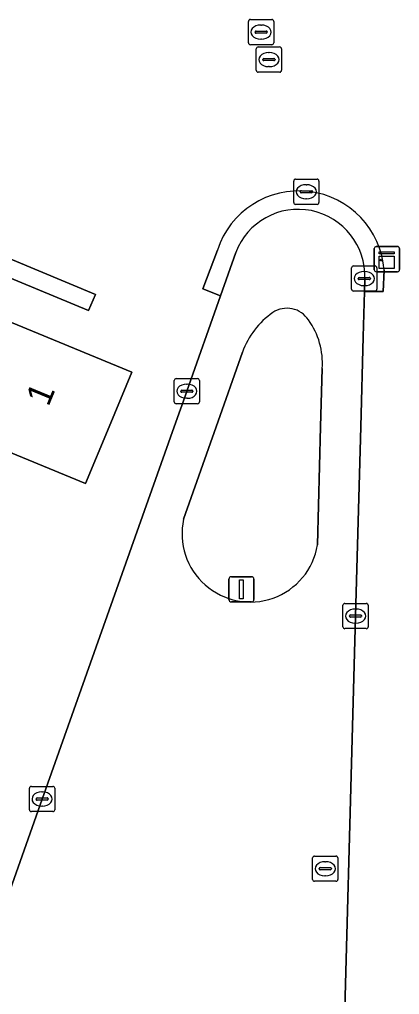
# Model space of a CAD drawing. Extents: x 160023 to 161302, y 384750 to 385707.
# Drawn here: x 160583.17 to 160598.24, y 384977.47 to 385016.17 of the extents above; entities that cross this region are included whole.
import ezdxf

# ---------------------------------------------------------------- set-up
doc = ezdxf.new("R2010")
doc.units = 0
for name, color, linetype in [('IMGEO_Brandkraan', 7, 'Continuous'), ('IMGEO_Erf', 7, 'Continuous'), ('IMGEO_Groenvoorziening', 7, 'Continuous'), ('IMGEO_Haag', 7, 'Continuous'), ('IMGEO_Kast', 7, 'Continuous'), ('IMGEO_Kolk', 7, 'Continuous'), ('IMGEO_Lichtmast', 7, 'Continuous'), ('IMGEO_Pand', 7, 'Continuous'), ('IMGEO_Pand_nummerreeks', 7, 'Continuous'), ('IMGEO_Rijbaan_lokaal_open', 7, 'Continuous'), ('IMGEO_Rioolput', 7, 'Continuous')]:
    doc.layers.add(name, color=color, linetype=linetype)

msp = doc.modelspace()

# ---------------------------------------------------------------- linework, layer by layer
at = {"layer": 'IMGEO_Brandkraan'}
for p, q in [((160594.797, 384982.034), (160594.797, 384982.886)), ((160594.872, 384982.96), (160595.724, 384982.96)), ((160595.285, 384982.74), (160595.31, 384982.74)), ((160595.798, 384982.886), (160595.798, 384982.034)), ((160595.056, 384982.454), (160595.056, 384982.466)), ((160595.494, 384982.417), (160595.096, 384982.417)), ((160595.099, 384982.503), (160595.497, 384982.503)), ((160595.54, 384982.466), (160595.54, 384982.454)), ((160595.724, 384981.96), (160594.872, 384981.96)), ((160595.308, 384982.18), (160595.283, 384982.18))]:
    msp.add_line(p, q, dxfattribs=at)
for points in [[(160594.797, 384982.034), (160594.797, 384982.886)], [(160594.872, 384982.96), (160595.724, 384982.96)], [(160595.798, 384982.886), (160595.798, 384982.034)], [(160595.724, 384981.96), (160594.872, 384981.96)]]:
    msp.add_lwpolyline(points, dxfattribs=at)
for centre, radius, start, end in [((160594.874, 384982.884), 0.0765, 91.552, 178.448), ((160594.874, 384982.884), 0.0765, 91.552, 178.448), ((160595.722, 384982.884), 0.0765, 1.552, 88.448), ((160595.722, 384982.884), 0.0765, 1.552, 88.448), ((160595.096, 384982.463), 0.0403, 85.8775, 175.7526), ((160595.093, 384982.453), 0.0366, 178.938, 274.7102), ((160595.497, 384982.46), 0.043, 264.8664, 352.4533), ((160595.501, 384982.465), 0.0386, 1.7309, 96.639), ((160594.874, 384982.036), 0.0765, 181.552, 268.448), ((160594.874, 384982.036), 0.0765, 181.552, 268.448), ((160595.722, 384982.036), 0.0765, 271.552, 358.448), ((160595.722, 384982.036), 0.0765, 271.552, 358.448)]:
    msp.add_arc(centre, radius, start, end, dxfattribs=at)
for centre, major_axis, ratio, start_param, end_param in [((160595.284, 384982.46), (-0.387, 0.002), 0.722429, 4.712389, 7.853982), ((160595.309, 384982.46), (-0.39, 0.002), 0.717154, 1.570796, 4.712389)]:
    msp.add_ellipse(centre, major_axis=major_axis, ratio=ratio, start_param=start_param, end_param=end_param, dxfattribs=at)
at = {"layer": 'IMGEO_Erf'}
for points in [[(160551.494, 384994.546), (160553.749, 385000), (160554.149, 385000.967), (160559.46, 385013.809), (160572.529, 385008.408), (160587.622, 385002.171), (160586.725, 385000), (160585.794, 384997.749), (160581.839, 384999.384), (160580.352, 384995.789), (160578.865, 384992.194), (160582.82, 384990.559), (160581.101, 384986.4), (160579.382, 384982.241), (160575.427, 384983.876), (160573.935, 384980.275), (160572.444, 384976.675)], [(160570.707, 384947.39), (160571.348, 384949.206), (160572.864, 384953.481), (160578.447, 384969.326), (160584.068, 384985.227), (160589.307, 385000), (160589.803, 385001.397), (160589.809, 385001.415), (160591.148, 385005.204), (160590.443, 385005.472), (160591.019, 385007.016)], [(160597.63, 385006.214), (160597.599, 385005.368), (160596.848, 385005.375), (160596.799, 385003.576), (160596.703, 385000), (160596.501, 384992.49), (160595.933, 384971.552), (160595.391, 384949.601)]]:
    msp.add_lwpolyline(points, dxfattribs=at)
msp.add_lwpolyline([(160573.447, 385009.785), (160573.728, 385010.449), (160586.183, 385005.251), (160585.915, 385004.616)], close=True, dxfattribs=at)
msp.add_arc((160594.247, 385005.973), 3.392, 4.08, 162.0861, dxfattribs=at)
at = {"layer": 'IMGEO_Groenvoorziening'}
msp.add_lwpolyline([(160586.183, 385005.251), (160573.728, 385010.449), (160573.447, 385009.785), (160585.915, 385004.616)], close=True, dxfattribs=at)
for points in [[(160591.019, 385007.016), (160590.443, 385005.472), (160591.148, 385005.204), (160591.751, 385006.921)], [(160596.865, 385005.886), (160596.848, 385005.375), (160597.599, 385005.368), (160597.63, 385006.214)], [(160592.015, 385002.963), (160590.972, 385000), (160589.682, 384996.333)], [(160594.993, 384995.31), (160595.115, 385000), (160595.176, 385002.317)]]:
    msp.add_lwpolyline(points, dxfattribs=at)
for centre, radius, start, end in [((160594.247, 385005.973), 3.392, 4.08, 162.0861), ((160594.224, 385005.99), 2.643, 357.7478, 159.3696), ((160595.117, 385001.842), 3.298, 125.1689, 160.1312), ((160593.778, 385003.691), 1.016, 32.7954, 123.4967), ((160592.282, 385002.538), 2.902, 355.6399, 35.936), ((160592.324, 384995.752), 2.705, 167.6046, 350.5899)]:
    msp.add_arc(centre, radius, start, end, dxfattribs=at)
at = {"layer": 'IMGEO_Haag'}
msp.add_lwpolyline([(160586.183, 385005.251), (160573.728, 385010.449), (160573.447, 385009.785), (160585.915, 385004.616)], close=True, dxfattribs=at)
for points in [[(160591.019, 385007.016), (160590.443, 385005.472), (160591.148, 385005.204), (160591.751, 385006.921)], [(160596.865, 385005.886), (160596.848, 385005.375), (160597.599, 385005.368), (160597.63, 385006.214)]]:
    msp.add_lwpolyline(points, dxfattribs=at)
for centre, radius, start, end in [((160594.247, 385005.973), 3.392, 4.08, 162.0861), ((160594.224, 385005.99), 2.643, 357.7478, 159.3696)]:
    msp.add_arc(centre, radius, start, end, dxfattribs=at)
at = {"layer": 'IMGEO_Kast'}
for p, q in [((160597.317, 385007.157), (160598.158, 385007.157)), ((160598.158, 385007.157), (160597.317, 385007.157)), ((160598.242, 385007.082), (160598.242, 385006.241)), ((160598.242, 385006.241), (160598.242, 385007.082)), ((160597.242, 385006.232), (160597.242, 385007.073)), ((160597.242, 385007.073), (160597.242, 385006.232)), ((160598.167, 385006.157), (160597.326, 385006.157)), ((160597.326, 385006.157), (160598.167, 385006.157))]:
    msp.add_line(p, q, dxfattribs=at)
for points in [[(160597.437, 385006.947), (160598.037, 385006.947), (160598.037, 385006.862), (160597.437, 385006.862), (160597.437, 385006.947)], [(160597.437, 385006.772), (160598.037, 385006.772), (160598.037, 385006.283), (160597.437, 385006.283), (160597.437, 385006.772)]]:
    msp.add_lwpolyline(points, dxfattribs=at)
msp.add_circle((160597.521, 385006.621), 0.0377, dxfattribs=at)
for centre, start, end in [((160597.32, 385007.079), 92.4484, 184.2845), ((160597.32, 385007.079), 92.4484, 184.2845), ((160598.164, 385007.079), 2.4484, 94.2845), ((160598.164, 385007.079), 2.4484, 94.2845), ((160597.32, 385006.235), 182.4484, 274.2845), ((160597.32, 385006.235), 182.4484, 274.2845), ((160598.164, 385006.235), 272.4484, 4.2845), ((160598.164, 385006.235), 272.4484, 4.2845)]:
    msp.add_arc(centre, 0.0779, start, end, dxfattribs=at)
at = {"layer": 'IMGEO_Kolk'}
for p, q in [((160594.123, 385009.831), (160594.975, 385009.831)), ((160594.048, 385008.905), (160594.048, 385009.757)), ((160594.536, 385009.611), (160594.561, 385009.611)), ((160595.049, 385009.757), (160595.049, 385008.905)), ((160594.307, 385009.325), (160594.307, 385009.337)), ((160594.745, 385009.288), (160594.347, 385009.288)), ((160594.35, 385009.374), (160594.748, 385009.374)), ((160594.559, 385009.051), (160594.534, 385009.051)), ((160594.791, 385009.337), (160594.791, 385009.325)), ((160594.975, 385008.831), (160594.123, 385008.831)), ((160596.344, 385005.46), (160596.344, 385006.312)), ((160596.419, 385006.386), (160597.271, 385006.386)), ((160597.345, 385006.312), (160597.345, 385005.46)), ((160596.646, 385005.929), (160597.044, 385005.929)), ((160596.832, 385006.166), (160596.857, 385006.166)), ((160596.603, 385005.88), (160596.603, 385005.892)), ((160597.041, 385005.843), (160596.643, 385005.843)), ((160596.855, 385005.606), (160596.83, 385005.606)), ((160597.087, 385005.892), (160597.087, 385005.88)), ((160597.271, 385005.386), (160596.419, 385005.386)), ((160589.309, 385000.988), (160589.309, 385001.84)), ((160589.384, 385001.914), (160590.236, 385001.914)), ((160589.797, 385001.694), (160589.822, 385001.694)), ((160590.31, 385001.84), (160590.31, 385000.988)), ((160589.568, 385001.408), (160589.568, 385001.42)), ((160590.006, 385001.371), (160589.608, 385001.371)), ((160589.611, 385001.457), (160590.009, 385001.457)), ((160590.052, 385001.42), (160590.052, 385001.408)), ((160590.236, 385000.914), (160589.384, 385000.914)), ((160589.82, 385001.134), (160589.795, 385001.134)), ((160595.999, 384992.063), (160595.999, 384992.915)), ((160596.074, 384992.989), (160596.926, 384992.989)), ((160596.487, 384992.769), (160596.512, 384992.769)), ((160597, 384992.915), (160597, 384992.063)), ((160596.258, 384992.483), (160596.258, 384992.495)), ((160596.696, 384992.446), (160596.298, 384992.446)), ((160596.301, 384992.532), (160596.699, 384992.532)), ((160596.742, 384992.495), (160596.742, 384992.483)), ((160596.926, 384991.989), (160596.074, 384991.989)), ((160596.51, 384992.209), (160596.485, 384992.209)), ((160583.568, 384984.801), (160583.568, 384985.653)), ((160583.643, 384985.727), (160584.495, 384985.727)), ((160584.056, 384985.507), (160584.081, 384985.507)), ((160584.569, 384985.653), (160584.569, 384984.801)), ((160583.827, 384985.221), (160583.827, 384985.233)), ((160584.265, 384985.184), (160583.867, 384985.184)), ((160583.87, 384985.27), (160584.268, 384985.27)), ((160584.311, 384985.233), (160584.311, 384985.221)), ((160584.495, 384984.727), (160583.643, 384984.727)), ((160584.079, 384984.947), (160584.054, 384984.947))]:
    msp.add_line(p, q, dxfattribs=at)
for points in [[(160594.123, 385009.831), (160594.975, 385009.831)], [(160594.048, 385008.905), (160594.048, 385009.757)], [(160595.049, 385009.757), (160595.049, 385008.905)], [(160594.975, 385008.831), (160594.123, 385008.831)], [(160596.344, 385005.46), (160596.344, 385006.312)], [(160596.419, 385006.386), (160597.271, 385006.386)], [(160597.345, 385006.312), (160597.345, 385005.46)], [(160597.271, 385005.386), (160596.419, 385005.386)], [(160589.309, 385000.988), (160589.309, 385001.84)], [(160589.384, 385001.914), (160590.236, 385001.914)], [(160590.31, 385001.84), (160590.31, 385000.988)], [(160590.236, 385000.914), (160589.384, 385000.914)], [(160595.999, 384992.063), (160595.999, 384992.915)], [(160596.074, 384992.989), (160596.926, 384992.989)], [(160597, 384992.915), (160597, 384992.063)], [(160596.926, 384991.989), (160596.074, 384991.989)], [(160583.568, 384984.801), (160583.568, 384985.653)], [(160583.643, 384985.727), (160584.495, 384985.727)], [(160584.569, 384985.653), (160584.569, 384984.801)], [(160584.495, 384984.727), (160583.643, 384984.727)]]:
    msp.add_lwpolyline(points, dxfattribs=at)
for centre, radius, start, end in [((160594.125, 385009.755), 0.0765, 91.552, 178.448), ((160594.125, 385009.755), 0.0765, 91.552, 178.448), ((160594.973, 385009.755), 0.0765, 1.552, 88.448), ((160594.973, 385009.755), 0.0765, 1.552, 88.448), ((160594.347, 385009.334), 0.0403, 85.8775, 175.7526), ((160594.344, 385009.324), 0.0366, 178.938, 274.7102), ((160594.748, 385009.331), 0.043, 264.8664, 352.4533), ((160594.752, 385009.336), 0.0386, 1.7309, 96.639), ((160594.125, 385008.907), 0.0765, 181.552, 268.448), ((160594.125, 385008.907), 0.0765, 181.552, 268.448), ((160594.973, 385008.907), 0.0765, 271.552, 358.448), ((160594.973, 385008.907), 0.0765, 271.552, 358.448), ((160596.421, 385006.31), 0.0765, 91.552, 178.448), ((160596.421, 385006.31), 0.0765, 91.552, 178.448), ((160597.269, 385006.31), 0.0765, 1.552, 88.448), ((160597.269, 385006.31), 0.0765, 1.552, 88.448), ((160596.643, 385005.889), 0.0403, 85.8775, 175.7526), ((160597.048, 385005.891), 0.0386, 1.7309, 96.639), ((160596.64, 385005.879), 0.0366, 178.938, 274.7102), ((160597.044, 385005.886), 0.043, 264.8664, 352.4533), ((160596.421, 385005.462), 0.0765, 181.552, 268.448), ((160596.421, 385005.462), 0.0765, 181.552, 268.448), ((160597.269, 385005.462), 0.0765, 271.552, 358.448), ((160597.269, 385005.462), 0.0765, 271.552, 358.448), ((160589.386, 385001.838), 0.0765, 91.552, 178.448), ((160589.386, 385001.838), 0.0765, 91.552, 178.448), ((160590.234, 385001.838), 0.0765, 1.552, 88.448), ((160590.234, 385001.838), 0.0765, 1.552, 88.448), ((160589.608, 385001.417), 0.0403, 85.8775, 175.7526), ((160589.605, 385001.407), 0.0366, 178.938, 274.7102), ((160590.009, 385001.414), 0.043, 264.8664, 352.4533), ((160590.013, 385001.419), 0.0386, 1.7309, 96.639), ((160589.386, 385000.99), 0.0765, 181.552, 268.448), ((160589.386, 385000.99), 0.0765, 181.552, 268.448), ((160590.234, 385000.99), 0.0765, 271.552, 358.448), ((160590.234, 385000.99), 0.0765, 271.552, 358.448), ((160596.076, 384992.913), 0.0765, 91.552, 178.448), ((160596.076, 384992.913), 0.0765, 91.552, 178.448), ((160596.924, 384992.913), 0.0765, 1.552, 88.448), ((160596.924, 384992.913), 0.0765, 1.552, 88.448), ((160596.298, 384992.492), 0.0403, 85.8775, 175.7526), ((160596.295, 384992.482), 0.0366, 178.938, 274.7102), ((160596.699, 384992.489), 0.043, 264.8664, 352.4533), ((160596.703, 384992.494), 0.0386, 1.7309, 96.639), ((160596.076, 384992.065), 0.0765, 181.552, 268.448), ((160596.076, 384992.065), 0.0765, 181.552, 268.448), ((160596.924, 384992.065), 0.0765, 271.552, 358.448), ((160596.924, 384992.065), 0.0765, 271.552, 358.448), ((160583.645, 384985.651), 0.0765, 91.552, 178.448), ((160583.645, 384985.651), 0.0765, 91.552, 178.448), ((160584.493, 384985.651), 0.0765, 1.552, 88.448), ((160584.493, 384985.651), 0.0765, 1.552, 88.448), ((160583.867, 384985.23), 0.0403, 85.8775, 175.7526), ((160583.864, 384985.22), 0.0366, 178.938, 274.7102), ((160584.268, 384985.227), 0.043, 264.8664, 352.4533), ((160584.272, 384985.232), 0.0386, 1.7309, 96.639), ((160583.645, 384984.803), 0.0765, 181.552, 268.448), ((160583.645, 384984.803), 0.0765, 181.552, 268.448), ((160584.493, 384984.803), 0.0765, 271.552, 358.448), ((160584.493, 384984.803), 0.0765, 271.552, 358.448)]:
    msp.add_arc(centre, radius, start, end, dxfattribs=at)
for centre, major_axis, ratio, start_param, end_param in [((160594.535, 385009.331), (-0.387, 0.002), 0.722429, 4.712389, 7.853982), ((160594.56, 385009.331), (-0.39, 0.002), 0.717154, 1.570796, 4.712389), ((160596.831, 385005.886), (-0.387, 0.002), 0.722429, 4.712389, 7.853982), ((160596.856, 385005.886), (-0.39, 0.002), 0.717154, 1.570796, 4.712389), ((160589.796, 385001.414), (-0.387, 0.002), 0.722429, 4.712389, 7.853982), ((160589.821, 385001.414), (-0.39, 0.002), 0.717154, 1.570796, 4.712389), ((160596.486, 384992.489), (-0.387, 0.002), 0.722429, 4.712389, 7.853982), ((160596.511, 384992.489), (-0.39, 0.002), 0.717154, 1.570796, 4.712389), ((160584.055, 384985.227), (-0.387, 0.002), 0.722429, 4.712389, 7.853982), ((160584.08, 384985.227), (-0.39, 0.002), 0.717154, 1.570796, 4.712389)]:
    msp.add_ellipse(centre, major_axis=major_axis, ratio=ratio, start_param=start_param, end_param=end_param, dxfattribs=at)
at = {"layer": 'IMGEO_Lichtmast'}
for p, q in [((160591.477, 384993.151), (160591.477, 384993.951)), ((160591.477, 384993.951), (160591.477, 384993.151)), ((160591.577, 384994.051), (160592.367, 384994.051)), ((160592.367, 384994.051), (160591.577, 384994.051)), ((160592.467, 384993.951), (160592.467, 384993.151)), ((160592.467, 384993.151), (160592.467, 384993.951)), ((160592.367, 384993.051), (160591.577, 384993.051)), ((160591.577, 384993.051), (160592.367, 384993.051))]:
    msp.add_line(p, q, dxfattribs=at)
msp.add_lwpolyline([(160591.897, 384993.926), (160592.047, 384993.926), (160592.047, 384993.176), (160591.897, 384993.176), (160591.897, 384993.926)], dxfattribs=at)
for centre, start, end in [((160591.577, 384993.951), 90, 180), ((160591.577, 384993.951), 90, 180), ((160592.367, 384993.951), 0, 90), ((160592.367, 384993.951), 360, 90), ((160591.577, 384993.151), 180, 270), ((160591.577, 384993.151), 180, 270), ((160592.367, 384993.151), 270, 0), ((160592.367, 384993.151), 270, 0)]:
    msp.add_arc(centre, 0.1, start, end, dxfattribs=at)
at = {"layer": 'IMGEO_Pand'}
msp.add_lwpolyline([(160572.529, 385008.408), (160569.125, 385000.202), (160570.145, 384999.777), (160570.237, 385000), (160572.91, 384998.887), (160573.528, 384998.63), (160573.678, 384998.567), (160573.802, 384998.516), (160575.284, 385002.104), (160578.83, 385000.628), (160577.338, 384997.044), (160580.352, 384995.789), (160581.839, 384999.384), (160585.794, 384997.749), (160586.725, 385000), (160587.622, 385002.171)], close=True, dxfattribs=at)
at = {"layer": 'IMGEO_Rijbaan_lokaal_open'}
for points in [[(160591.751, 385006.921), (160591.148, 385005.204), (160589.809, 385001.415), (160589.803, 385001.397), (160589.307, 385000), (160584.068, 384985.227), (160578.447, 384969.326), (160572.864, 384953.481), (160571.348, 384949.206), (160570.707, 384947.39)], [(160595.933, 384971.552), (160596.501, 384992.49), (160596.703, 385000), (160596.799, 385003.576), (160596.848, 385005.375), (160596.865, 385005.886)], [(160589.682, 384996.333), (160590.972, 385000), (160592.015, 385002.963)], [(160595.176, 385002.317), (160595.115, 385000), (160594.993, 384995.31)]]:
    msp.add_lwpolyline(points, dxfattribs=at)
for centre, radius, start, end in [((160594.224, 385005.99), 2.643, 357.7478, 159.3696), ((160595.117, 385001.842), 3.298, 125.1689, 160.1312), ((160593.778, 385003.691), 1.016, 32.7954, 123.4967), ((160592.282, 385002.538), 2.902, 355.6399, 35.936), ((160592.324, 384995.752), 2.705, 167.6046, 350.5899)]:
    msp.add_arc(centre, radius, start, end, dxfattribs=at)
at = {"layer": 'IMGEO_Rioolput'}
for p, q in [((160592.253, 385015.242), (160592.253, 385016.094)), ((160592.328, 385016.168), (160593.18, 385016.168)), ((160593.254, 385016.094), (160593.254, 385015.242)), ((160592.512, 385015.662), (160592.512, 385015.674)), ((160592.95, 385015.625), (160592.552, 385015.625)), ((160592.555, 385015.711), (160592.953, 385015.711)), ((160592.741, 385015.948), (160592.766, 385015.948)), ((160592.996, 385015.674), (160592.996, 385015.662)), ((160592.764, 385015.388), (160592.739, 385015.388)), ((160593.18, 385015.168), (160592.328, 385015.168)), ((160592.563, 385014.152), (160592.563, 385015.004)), ((160592.638, 385015.078), (160593.49, 385015.078)), ((160593.051, 385014.858), (160593.076, 385014.858)), ((160593.564, 385015.004), (160593.564, 385014.152)), ((160592.822, 385014.572), (160592.822, 385014.584)), ((160593.26, 385014.535), (160592.862, 385014.535)), ((160592.865, 385014.621), (160593.263, 385014.621)), ((160593.306, 385014.584), (160593.306, 385014.572)), ((160593.49, 385014.078), (160592.638, 385014.078)), ((160593.074, 385014.298), (160593.049, 385014.298))]:
    msp.add_line(p, q, dxfattribs=at)
for points in [[(160592.253, 385015.242), (160592.253, 385016.094)], [(160592.328, 385016.168), (160593.18, 385016.168)], [(160593.254, 385016.094), (160593.254, 385015.242)], [(160593.18, 385015.168), (160592.328, 385015.168)], [(160592.563, 385014.152), (160592.563, 385015.004)], [(160592.638, 385015.078), (160593.49, 385015.078)], [(160593.564, 385015.004), (160593.564, 385014.152)], [(160593.49, 385014.078), (160592.638, 385014.078)]]:
    msp.add_lwpolyline(points, dxfattribs=at)
for centre, radius, start, end in [((160592.33, 385016.092), 0.0765, 91.552, 178.448), ((160592.33, 385016.092), 0.0765, 91.552, 178.448), ((160593.178, 385016.092), 0.0765, 1.552, 88.448), ((160593.178, 385016.092), 0.0765, 1.552, 88.448), ((160592.552, 385015.671), 0.0403, 85.8775, 175.7526), ((160592.549, 385015.661), 0.0366, 178.938, 274.7102), ((160592.953, 385015.668), 0.043, 264.8664, 352.4533), ((160592.957, 385015.673), 0.0386, 1.7309, 96.639), ((160592.33, 385015.244), 0.0765, 181.552, 268.448), ((160592.33, 385015.244), 0.0765, 181.552, 268.448), ((160593.178, 385015.244), 0.0765, 271.552, 358.448), ((160593.178, 385015.244), 0.0765, 271.552, 358.448), ((160592.64, 385015.002), 0.0765, 91.552, 178.448), ((160592.64, 385015.002), 0.0765, 91.552, 178.448), ((160593.488, 385015.002), 0.0765, 1.552, 88.448), ((160593.488, 385015.002), 0.0765, 1.552, 88.448), ((160592.862, 385014.581), 0.0403, 85.8775, 175.7526), ((160592.859, 385014.571), 0.0366, 178.938, 274.7102), ((160593.263, 385014.578), 0.043, 264.8664, 352.4533), ((160593.267, 385014.583), 0.0386, 1.7309, 96.639), ((160592.64, 385014.154), 0.0765, 181.552, 268.448), ((160592.64, 385014.154), 0.0765, 181.552, 268.448), ((160593.488, 385014.154), 0.0765, 271.552, 358.448), ((160593.488, 385014.154), 0.0765, 271.552, 358.448)]:
    msp.add_arc(centre, radius, start, end, dxfattribs=at)
for centre, major_axis, ratio, start_param, end_param in [((160592.74, 385015.668), (-0.387, 0.002), 0.722429, 4.712389, 7.853982), ((160592.765, 385015.668), (-0.39, 0.002), 0.717154, 1.570796, 4.712389), ((160593.05, 385014.578), (-0.387, 0.002), 0.722429, 4.712389, 7.853982), ((160593.075, 385014.578), (-0.39, 0.002), 0.717154, 1.570796, 4.712389)]:
    msp.add_ellipse(centre, major_axis=major_axis, ratio=ratio, start_param=start_param, end_param=end_param, dxfattribs=at)

# ---------------------------------------------------------------- texts
at = {"layer": 'IMGEO_Pand_nummerreeks'}
msp.add_text('1', height=1, rotation=67.5403, dxfattribs=at).set_placement((160584.318, 385000.774))

doc.saveas('drawing.dxf')
